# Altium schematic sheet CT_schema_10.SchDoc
size 384 x 385 mm
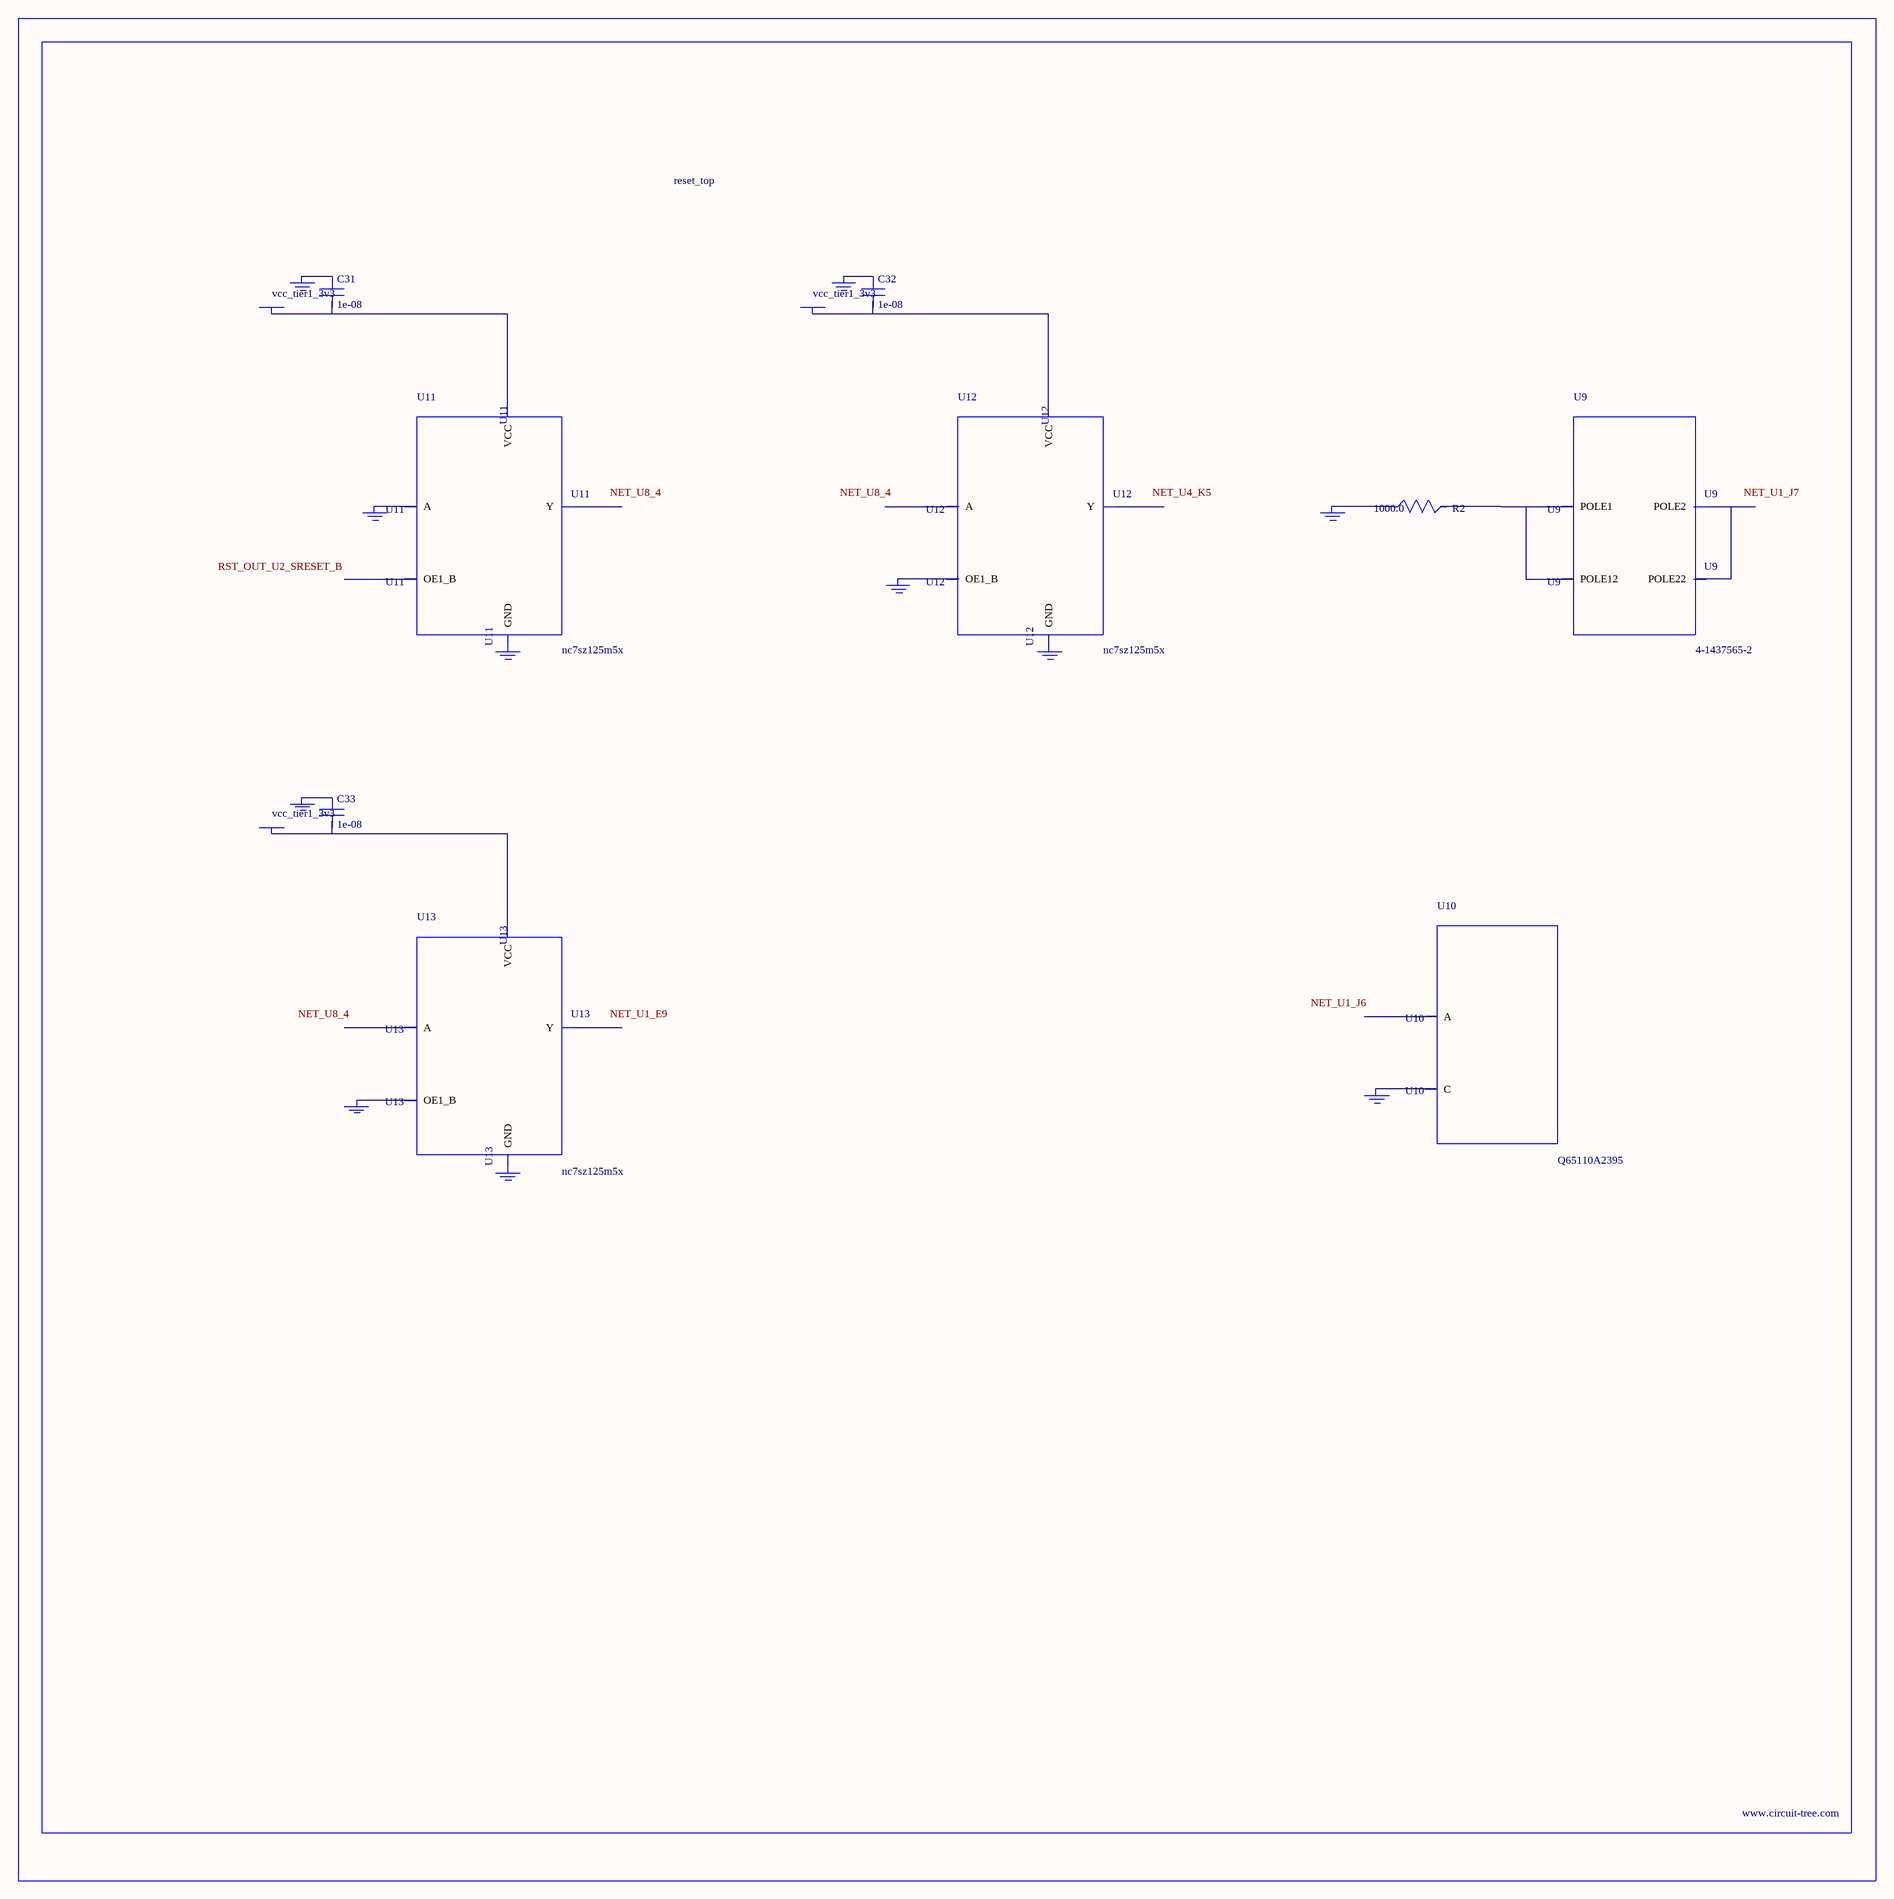
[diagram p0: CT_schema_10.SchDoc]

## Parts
BORDER9  (no value)
C31  1e-08  [C0402]
C32  1e-08  [C0402]
C33  1e-08  [C0402]
GND_INSTANCE_9_0  (no value)
GND_INSTANCE_9_1  (no value)
GND_INSTANCE_9_2  (no value)
GND_INSTANCE_9_3  (no value)
GND_INSTANCE_9_4  (no value)
GND_INSTANCE_9_5  (no value)
GND_INSTANCE_9_6  (no value)
GND_INSTANCE_9_7  (no value)
GND_INSTANCE_9_8  (no value)
GND_INSTANCE_9_9  (no value)
GND_INSTANCE_9_10  (no value)
POWER_INSTANCE_9_0  vcc_tier1_3v3
POWER_INSTANCE_9_1  vcc_tier1_3v3
POWER_INSTANCE_9_2  vcc_tier1_3v3
R2  1000.0  [R0603]
U9  4-1437565-2  [SW_4-1437565-2]
U10  Q65110A2395  [LGM67K-G1J2-24-Z]
U11  nc7sz125m5x  [NC7SZ125M5X]
U12  nc7sz125m5x  [NC7SZ125M5X]
U13  nc7sz125m5x  [NC7SZ125M5X]

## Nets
NetC31_1: C31.1 GND_INSTANCE_9_2.0(GND)
NetC31_2: C31.2 POWER_INSTANCE_9_0.0(PWR) U11.5(VCC)
NetC32_1: C32.1 GND_INSTANCE_9_5.0(GND)
NetC32_2: C32.2 POWER_INSTANCE_9_1.0(PWR) U12.5(VCC)
NetC33_1: C33.1 GND_INSTANCE_9_8.0(GND)
NetC33_2: C33.2 POWER_INSTANCE_9_2.0(PWR) U13.5(VCC)
NetGND_INSTANCE_9_0_0: GND_INSTANCE_9_0.0(GND) R2.1
NetGND_INSTANCE_9_1_0: GND_INSTANCE_9_1.0(GND) U10.C
NetGND_INSTANCE_9_3_0: GND_INSTANCE_9_3.0(GND) U11.2(A)
NetGND_INSTANCE_9_4_0: GND_INSTANCE_9_4.0(GND) U11.3(GND)
NetGND_INSTANCE_9_6_0: GND_INSTANCE_9_6.0(GND) U12.1(OE1_B)
NetGND_INSTANCE_9_7_0: GND_INSTANCE_9_7.0(GND) U12.3(GND)
NetGND_INSTANCE_9_9_0: GND_INSTANCE_9_9.0(GND) U13.1(OE1_B)
NetGND_INSTANCE_9_10_0: GND_INSTANCE_9_10.0(GND) U13.3(GND)
NetR2_2: R2.2 U9.1(POLE1) U9.2(POLE12)
NetU9_3: U9.3(POLE2) U9.4(POLE22)

Not connected (* = marked no-connect by the designer): U10 A; U11 1(OE1_B) 4(Y); U12 2(A) 4(Y); U13 2(A) 4(Y)

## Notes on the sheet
- Labels drawn without touching a wire or pin: NET_U1_E9, NET_U1_J6, NET_U1_J7, NET_U4_K5, NET_U8_4, RST_OUT_U2_SRESET_B

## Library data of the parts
BORDER9 = BORDER_PAGE9
C31-C33 = C0402C103K3RAC
GND_INSTANCE_9_0-GND_INSTANCE_9_10 = GND
POWER_INSTANCE_9_0-POWER_INSTANCE_9_2 = PWR
R2 = RC0603JR-071KL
